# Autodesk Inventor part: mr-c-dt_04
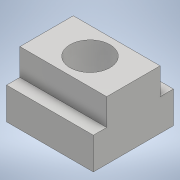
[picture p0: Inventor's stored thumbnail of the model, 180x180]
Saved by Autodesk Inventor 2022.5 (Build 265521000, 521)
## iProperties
Part Number: mr-c-dt_04
Material: 一般
Document SubType Name: Modeling
Designer: ImaoCorp
Density: 1 g/cm^3
Appearance: 既定
Author: ImaoCorp
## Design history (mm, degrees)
feature "mr-c-dt_04"
node "ソリッド1"
